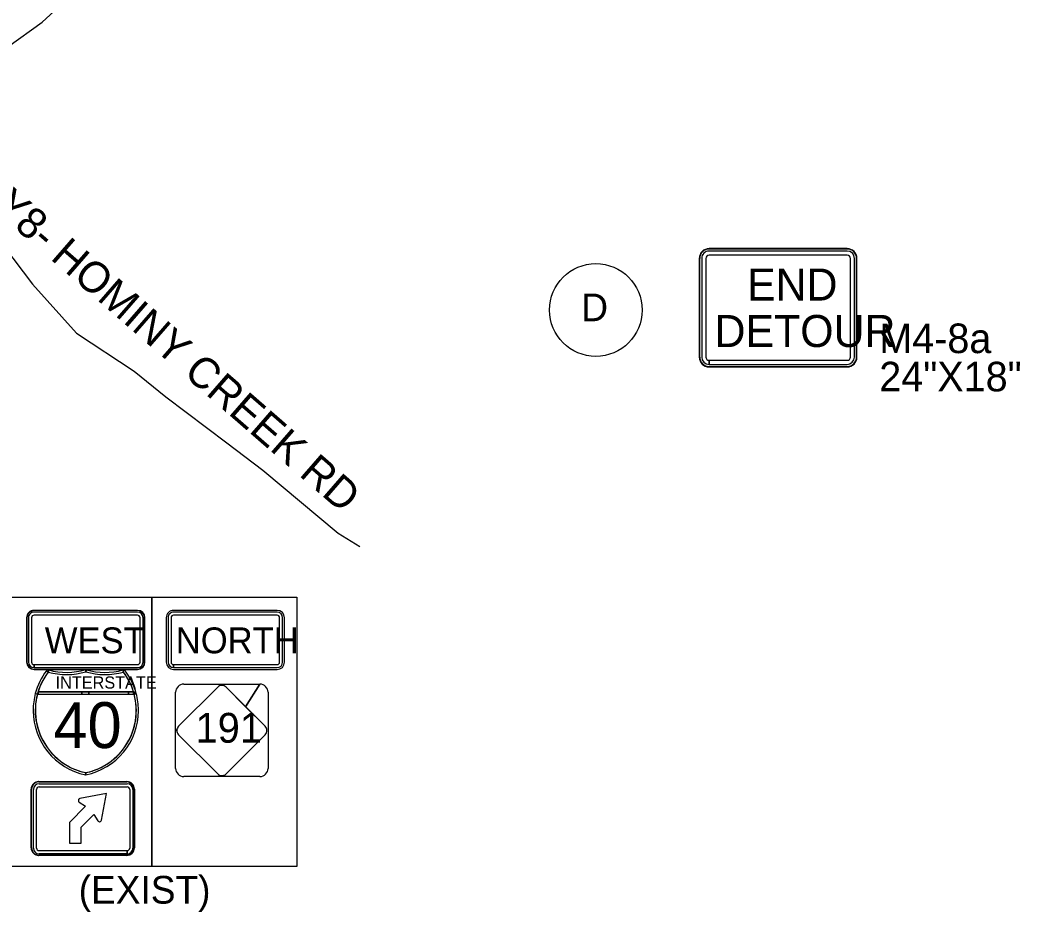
# Model space of a CAD drawing. Extents: x 886234 to 968767, y 455416 to 684046.
# Drawn here: x 917582 to 921641, y 510908 to 514526 of the extents above; entities that cross this region are included whole.
import ezdxf

# ---------------------------------------------------------------- set-up
doc = ezdxf.new("R2010")
doc.units = 0
for name, color, linetype in [('TC DEV SIGN BLACK 239', 7, 'Continuous'), ('TC DEV SIGN BLACK ZERO', 7, 'Continuous'), ('TC DEV SIGN ORANGE', 7, 'Continuous'), ('TC DEV SIGN WHITE', 7, 'Continuous'), ('TC LABEL TEXT', 7, 'Continuous')]:
    doc.layers.add(name, color=color, linetype=linetype)

msp = doc.modelspace()

# ---------------------------------------------------------------- linework, layer by layer
at = {"layer": 'TC DEV SIGN BLACK 239'}
for p, q in [((918059.5, 512124.1), (917639.5, 512124.1)), ((918625.9, 512124.1), (918205.8, 512124.1)), ((918625.9, 512124.1), (918205.8, 512124.1)), ((917617, 512101.6), (917617, 511921.6)), ((917629.5, 512101.6), (917629.5, 511921.6)), ((918059.5, 512111.6), (917639.5, 512111.6)), ((918069.5, 511921.6), (918069.5, 512101.6)), ((918082, 511921.6), (918082, 512101.6)), ((918183.3, 512101.6), (918183.3, 511921.6)), ((918183.3, 512101.6), (918183.3, 511921.6)), ((918195.8, 512101.6), (918195.8, 511921.6)), ((918195.8, 512101.6), (918195.8, 511921.6)), ((918625.9, 512111.6), (918205.8, 512111.6)), ((918625.9, 512111.6), (918205.8, 512111.6)), ((918635.9, 511921.6), (918635.9, 512101.6)), ((918635.9, 511921.6), (918635.9, 512101.6)), ((918648.4, 511921.6), (918648.4, 512101.6)), ((918648.4, 511921.6), (918648.4, 512101.6)), ((917639.5, 511899.1), (917639.5, 511911.6)), ((917639.6, 511911.6), (918059.5, 511911.6)), ((917639.6, 511911.6), (917639.6, 511899.1)), ((917639.6, 511899.1), (918059.5, 511899.1)), ((918205.8, 511899.1), (918205.8, 511911.6)), ((918205.8, 511899.1), (918205.8, 511911.6)), ((918205.9, 511911.6), (918625.9, 511911.6)), ((918205.9, 511911.6), (918205.9, 511899.1)), ((918205.9, 511911.6), (918625.9, 511911.6)), ((918205.9, 511911.6), (918205.9, 511899.1)), ((918205.9, 511899.1), (918625.9, 511899.1)), ((918205.9, 511899.1), (918625.9, 511899.1)), ((918214.1, 511645.6), (918214.1, 511799.1)), ((918214.1, 511645.6), (918214.1, 511799.1)), ((918384.8, 511819.9), (918226, 511661.1)), ((918247.2, 511832.2), (918401.6, 511832.2)), ((918247.2, 511832.2), (918247.2, 511832.2)), ((918247.2, 511832.2), (918556, 511832.2)), ((918247.2, 511832.2), (918247.2, 511832.2)), ((918401.6, 511832.2), (918556, 511832.2)), ((918498.2, 511740.5), (918556, 511832.2)), ((918589.1, 511799.1), (918589.1, 511490.3)), ((918589.1, 511799.1), (918589.1, 511490.3)), ((918577.6, 511661.1), (918498.2, 511740.5)), ((918219, 511645.6), (918214.1, 511645.6)), ((918214.1, 511645.5), (918219, 511645.5)), ((918214.1, 511490.3), (918214.1, 511645.5)), ((918214.1, 511490.3), (918214.1, 511645.5)), ((918226, 511627.1), (918384.8, 511468.3)), ((918418.8, 511468.3), (918577.6, 511627.1)), ((918556, 511457.2), (918247.2, 511457.2)), ((918401.6, 511457.2), (918247.2, 511457.2)), ((918556, 511457.2), (918401.6, 511457.2)), ((917636.9, 511166.8), (917636.9, 511405.3)), ((917649.6, 511166.8), (917649.6, 511405.3)), ((917659.7, 511428.1), (918017.5, 511428.1)), ((917659.7, 511415.5), (918017.5, 511415.5)), ((918027.7, 511405.3), (918027.7, 511166.8)), ((918040.3, 511405.3), (918040.3, 511166.8)), ((918017.4, 511156.6), (917659.7, 511156.6)), ((918017.4, 511156.6), (918017.4, 511144)), ((918017.5, 511144), (918017.5, 511156.6)), ((918017.4, 511144), (917659.7, 511144))]:
    msp.add_line(p, q, dxfattribs=at)
for points in [[(918556, 511832.2), (918498.2, 511740.5), (918418.8, 511819.9)], [(917830.3, 511251.4), (917882.3, 511303.5), (917898.7, 511277.5), (917900.2, 511275.8), (917902, 511274.6), (917904.9, 511273.8), (917906.9, 511274), (917908.7, 511274.5), (917911.1, 511276.2), (917912.5, 511278.2), (917913.2, 511280.3), (917933, 511388), (917825.8, 511367.7), (917824, 511367.2), (917822.8, 511366.4), (917821.3, 511365.1), (917820.2, 511363.6), (917819.5, 511361.4), (917819.5, 511358.7), (917820.2, 511356.4), (917821.5, 511354.4), (917823, 511353.2), (917848.8, 511336.9), (917782.9, 511271)], [(917782.9, 511271), (917782.9, 511187.7), (917830.3, 511187.7), (917830.3, 511251.4)]]:
    msp.add_lwpolyline(points, dxfattribs=at)
for centre, radius, start, end in [((918247.2, 511799.1), 33.1, 90, 180), ((918247.2, 511799.1), 33.1, 90, 180), ((918401.8, 511802.9), 24.1, 93.2102, 135), ((918401.8, 511802.9), 24.1, 45, 93.0763), ((918556, 511799.1), 33.1, 360, 90), ((918556, 511799.1), 33.1, 360, 90), ((918243, 511644.1), 24.1, 176.5595, 225), ((918243, 511644.1), 24.1, 135, 176.407), ((918560.6, 511644.1), 24.1, 1.9293, 45), ((918560.6, 511644.1), 24.1, 315, 1.7382), ((918247.2, 511490.3), 33.1, 180, 270), ((918247.2, 511490.3), 33.1, 180, 270), ((918556, 511490.3), 33.1, 270, 360), ((918556, 511490.3), 33.1, 270, 360), ((918401.8, 511485.3), 24.1, 225, 265.0473), ((918401.8, 511485.3), 24.1, 265.1815, 315)]:
    msp.add_arc(centre, radius, start, end, dxfattribs=at)
for centre, major_axis, start_param, end_param in [((917639.5, 512101.6), (22.5, 0), 1.570796, 3.141593), ((918059.5, 512101.6), (22.5, 0), 0, 1.570796), ((918205.8, 512101.6), (22.5, 0), 1.570796, 3.141593), ((918205.8, 512101.6), (22.5, 0), 1.570796, 3.141593), ((918625.9, 512101.6), (22.5, 0), 0, 1.570796), ((918625.9, 512101.6), (22.5, 0), 0, 1.570796), ((917639.5, 512101.6), (10, 0), 1.570796, 3.141593), ((918059.5, 512101.6), (10, 0), 0, 1.570796), ((918205.8, 512101.6), (10, 0), 1.570796, 3.141593), ((918205.8, 512101.6), (10, 0), 1.570796, 3.141593), ((918625.9, 512101.6), (10, 0), 0, 1.570796), ((918625.9, 512101.6), (10, 0), 0, 1.570796), ((917639.5, 511921.6), (22.5, 0), 3.141593, 4.712389), ((917639.5, 511921.6), (10, 0), 3.141593, 4.712389), ((918059.5, 511921.6), (22.5, 0), 4.712389, 6.283185), ((918059.5, 511921.6), (10, 0), 4.712389, 6.283185), ((918205.8, 511921.6), (22.5, 0), 3.141593, 4.712389), ((918205.8, 511921.6), (22.5, 0), 3.141593, 4.712389), ((918205.8, 511921.6), (10, 0), 3.141593, 4.712389), ((918205.8, 511921.6), (10, 0), 3.141593, 4.712389), ((918625.9, 511921.6), (22.5, 0), 4.712389, 6.283185), ((918625.9, 511921.6), (10, 0), 4.712389, 6.283185), ((918625.9, 511921.6), (22.5, 0), 4.712389, 6.283185), ((918625.9, 511921.6), (10, 0), 4.712389, 6.283185), ((917659.7, 511405.3), (-22.8, 0), 4.712389, 6.283185), ((917659.7, 511405.3), (-10.1, 0), 4.712389, 6.283185), ((918017.5, 511405.3), (-22.8, 0), 3.141593, 4.712389), ((918017.5, 511405.3), (-10.1, 0), 3.141593, 4.712389), ((917659.7, 511166.8), (-22.8, 0), 0, 1.570796), ((917659.7, 511166.8), (-10.1, 0), 0, 1.570796), ((918017.5, 511166.8), (-22.8, 0), 1.570796, 3.141593), ((918017.5, 511166.8), (-10.1, 0), 1.570796, 3.141593)]:
    msp.add_ellipse(centre, major_axis=major_axis, ratio=0.999865, start_param=start_param, end_param=end_param, dxfattribs=at)
at = {"layer": 'TC DEV SIGN BLACK ZERO'}
for p, q in [((920939.2, 513599.1), (920379.1, 513599.1)), ((920379.1, 513597.4), (920379.1, 513597.4)), ((920939.2, 513597.4), (920379.1, 513597.4)), ((920939.2, 513589.1), (920379.1, 513589.1)), ((920939.2, 513597.4), (920939.2, 513597.4)), ((920339.1, 513559.1), (920339, 513159.1)), ((920340.7, 513559.1), (920340.7, 513159.1)), ((920340.7, 513559.1), (920340.7, 513559.1)), ((920349.1, 513559.1), (920349, 513159.1)), ((920365.7, 513559.1), (920365.7, 513159.1)), ((920939.2, 513572.4), (920379.1, 513572.4)), ((920952.5, 513159.1), (920952.5, 513559.1)), ((920969.1, 513159.1), (920969.2, 513559.1)), ((920977.5, 513559.1), (920977.5, 513559.1)), ((920977.5, 513159.1), (920977.5, 513559.1)), ((920979.1, 513159.1), (920979.2, 513559.1)), ((920340.7, 513159.1), (920340.7, 513159.1)), ((920379.1, 513129.1), (920379.1, 513145.8)), ((920379.2, 513145.8), (920939.1, 513145.8)), ((920379.2, 513145.8), (920379.2, 513129.1)), ((920977.5, 513159.1), (920977.5, 513159.1)), ((920379.1, 513119.1), (920379.1, 513120.8)), ((920379.1, 513120.8), (920379.1, 513120.8)), ((920379.1, 513120.8), (920939.1, 513120.8)), ((920379.1, 513120.8), (920379.1, 513119.1)), ((920379.1, 513119.1), (920939.1, 513119.1)), ((920379.2, 513129.1), (920939.1, 513129.1)), ((920939.1, 513120.8), (920939.1, 513120.8)), ((918059.5, 512131.6), (917639.5, 512131.6)), ((917639.5, 512130.3), (917639.5, 512130.4)), ((918059.5, 512130.3), (917639.5, 512130.4)), ((918059.5, 512130.3), (918059.5, 512130.3)), ((917609.5, 512101.6), (917609.5, 511921.6)), ((917610.7, 512101.6), (917610.7, 511921.6)), ((917610.7, 512101.6), (917610.7, 512101.6)), ((918088.3, 512101.6), (918088.3, 512101.6)), ((918088.3, 511921.6), (918088.3, 512101.6)), ((918089.5, 511921.6), (918089.5, 512101.6)), ((917610.7, 511921.6), (917610.7, 511921.6)), ((918088.3, 511921.6), (918088.3, 511921.6)), ((917639.5, 511891.6), (917639.5, 511892.8)), ((917639.5, 511892.8), (917639.5, 511892.8)), ((917639.5, 511892.8), (918059.5, 511892.8)), ((917639.5, 511892.8), (917639.5, 511891.6)), ((917639.5, 511891.6), (918059.5, 511891.6)), ((917696.7, 511881.3), (917699.1, 511889.9)), ((917849.8, 511882.3), (917849.5, 511891.6)), ((917849.7, 511883), (917849.5, 511891.6)), ((917999.9, 511889.9), (918002.4, 511881.3)), ((918059.5, 511892.8), (918059.5, 511892.8)), ((917655.7, 511800.4), (918043.4, 511800.4)), ((917833.2, 511800.4), (917655.7, 511800.4)), ((917861.3, 511800.4), (917833.2, 511800.4)), ((918022.4, 511800.4), (917861.3, 511800.4)), ((918043.4, 511800.4), (918022.4, 511800.4)), ((918054.5, 511793.8), (918043.4, 511800.4)), ((917653.2, 511791.5), (918045.9, 511791.5)), ((917653.2, 511791.5), (917655.7, 511791.5)), ((917655.7, 511791.5), (917833.2, 511791.5)), ((917833.2, 511791.5), (917861.3, 511791.5)), ((917861.3, 511791.5), (918022.4, 511791.5)), ((918022.4, 511791.5), (918043.4, 511791.5)), ((918045.7, 511792.1), (918043.4, 511791.5)), ((918043.4, 511791.5), (918045.9, 511791.5)), ((917635.8, 511727.2), (917635.8, 511724.6)), ((918063.3, 511724.5), (918063.3, 511727.3)), ((917849.5, 511464.1), (917849.5, 511473.2)), ((917658.4, 511436.8), (918016.1, 511436.8)), ((917658.4, 511435.5), (918016.1, 511435.5)), ((917658.4, 511435.5), (917658.4, 511435.5)), ((918016.1, 511435.5), (918016.1, 511435.5)), ((917627.9, 511167.8), (917627.9, 511406.4)), ((917629.2, 511406.4), (917629.2, 511406.4)), ((917629.2, 511167.8), (917629.2, 511406.4)), ((918045.3, 511406.4), (918045.3, 511167.8)), ((918045.3, 511406.4), (918045.3, 511406.4)), ((918046.6, 511406.4), (918046.6, 511167.8)), ((917629.2, 511167.8), (917629.2, 511167.8)), ((918045.3, 511167.8), (918045.3, 511167.8)), ((917658.4, 511138.7), (917658.4, 511138.7)), ((918016.1, 511138.7), (917658.4, 511138.7)), ((918016.1, 511137.4), (917658.4, 511137.4)), ((918016.1, 511137.4), (918016.1, 511138.7)), ((918016.1, 511138.7), (918016.1, 511138.7)), ((918016.1, 511138.7), (918016.1, 511137.4))]:
    msp.add_line(p, q, dxfattribs=at)
for points in [[(917689.6, 511886.7), (917696.7, 511881.3)], [(917696.7, 511881.3), (917689.6, 511886.7)], [(917693.4, 511891.6), (917693.4, 511891.6), (917693.4, 511891.6)], [(917699.1, 511889.9), (917696.7, 511881.3)], [(917849.5, 511882.3), (917849.7, 511883)], [(917849.7, 511891.5), (917849.7, 511883), (917852.3, 511890.8)], [(917852.3, 511890.8), (917849.8, 511882.3)], [(918002.4, 511881.3), (917999.9, 511889.9)], [(918005.7, 511891.6), (918005.7, 511891.6), (918005.7, 511891.6)], [(917655.7, 511800.4), (917655.7, 511791.5)], [(917655.7, 511791.5), (917655.7, 511800.4)], [(917833.2, 511791.5), (917833.2, 511800.4)], [(917833.2, 511800.4), (917833.2, 511791.5)], [(917861.3, 511800.4), (917861.3, 511791.5)], [(917861.3, 511791.5), (917861.3, 511800.4)], [(918022.4, 511791.5), (918022.4, 511800.4)], [(918022.4, 511800.4), (918022.4, 511791.5)], [(918043.4, 511800.4), (918054.5, 511793.8)], [(918043.4, 511791.5), (918043.4, 511800.4)], [(918043.4, 511800.4), (918043.4, 511791.5), (918045.7, 511792.1), (918043.4, 511800.4)], [(917644.5, 511793.8), (917653.2, 511791.5)], [(917653.2, 511791.5), (917644.5, 511793.8)], [(918045.9, 511791.5), (918045.7, 511792.1)], [(918054.5, 511793.8), (918045.9, 511791.5)], [(918045.9, 511791.5), (918054.5, 511793.8)], [(917847.7, 511464.5), (917849.5, 511473.2)], [(917849.5, 511473.2), (917847.7, 511464.5), (917849.5, 511464.1)], [(917849.5, 511473.2), (917849.5, 511464.1)]]:
    msp.add_lwpolyline(points, dxfattribs=at)
for centre, radius, start, end in [((917903, 511725.9), 267.2, 142.9968, 165.2769), ((917903, 511725.9), 258.3, 142.9968, 258.0595), ((917903, 511725.9), 258.3, 142.9968, 165.2769), ((917903, 511725.9), 267.2, 141.6709, 142.9968), ((917771.5, 512147.1), 267.2, 253.0099, 254.2907), ((917771.5, 512147.1), 276.1, 254.2907, 286.4259), ((917771.5, 512147.1), 276.1, 254.2907, 286.4259), ((917771.5, 512147.1), 267.2, 254.2907, 286.9893), ((917927.6, 512147.1), 276.1, 253.5741, 285.7093), ((917796.1, 511725.9), 258.3, 281.9405, 37.0032), ((917927.6, 512147.1), 267.2, 253.0588, 253.6206), ((917927.7, 512146.7), 275.7, 253.5731, 285.7093), ((917927.6, 512147.1), 267.2, 253.6206, 285.7093), ((917927.6, 512147.1), 267.2, 285.7093, 286.9901), ((917796.1, 511725.9), 258.3, 16.7759, 37.0032), ((917796.1, 511725.9), 267.2, 14.7231, 38.3291), ((917903, 511725.9), 258.3, 163.2241, 165.2769), ((917796.1, 511725.9), 258.3, 14.7231, 16.7759), ((917903, 511725.9), 267.2, 165.2769, 179.7177), ((917901.7, 511725.1), 257.3, 165.0438, 258.3001), ((917797.4, 511725.1), 257.3, 281.7196, 14.964), ((917796.1, 511725.9), 267.2, 0.2997, 14.7231), ((917903, 511725.9), 267.2, 180.2823, 258.0591), ((917796.1, 511725.9), 267.2, 281.537, 359.7003), ((917796.1, 511725.9), 258.3, 281.9405, 281.9604), ((917903, 511725.9), 267.2, 258.458, 258.463), ((917796.1, 511725.9), 267.2, 281.5369590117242, 281.53700435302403)]:
    msp.add_arc(centre, radius, start, end, dxfattribs=at)
for centre, major_axis, start_param, end_param in [((920379.1, 513559.1), (40, 0), 1.570796, 3.141593), ((920379.1, 513559.1), (38.3, 0), 1.570796, 3.141593), ((920379.1, 513559.1), (30, 0), 1.570796, 3.141593), ((920939.2, 513559.1), (40, 0), 0, 1.570796), ((920939.2, 513559.1), (38.3, 0), 0, 1.570796), ((920939.2, 513559.1), (30, 0), 0, 1.570796), ((920379.1, 513559.1), (13.3, 0), 1.570796, 3.141593), ((920939.2, 513559.1), (13.3, 0), 0, 1.570796), ((920379.1, 513159.1), (40, 0), 3.141593, 4.712389), ((920379.1, 513159.1), (38.3, 0), 3.141593, 4.712389), ((920379.1, 513159.1), (30, 0), 3.141593, 4.712389), ((920379.1, 513159.1), (13.3, 0), 3.141593, 4.712389), ((920939.1, 513159.1), (30, 0), 4.712389, 6.283185), ((920939.1, 513159.1), (13.3, 0), 4.712389, 6.283185), ((920939.1, 513159.1), (40, 0), 4.712389, 6.283185), ((920939.1, 513159.1), (38.3, 0), 4.712389, 6.283185), ((917639.5, 512101.6), (30, 0), 1.570796, 3.141593), ((917639.5, 512101.6), (28.8, 0), 1.570796, 3.141593), ((918059.5, 512101.6), (30, 0), 0, 1.570796), ((918059.5, 512101.6), (28.8, 0), 0, 1.570796), ((917639.5, 511921.6), (30, 0), 3.141593, 4.712389), ((917639.5, 511921.6), (28.8, 0), 3.141593, 4.712389), ((918059.5, 511921.6), (30, 0), 4.712389, 6.283185), ((918059.5, 511921.6), (28.8, 0), 4.712389, 6.283185), ((917658.4, 511406.4), (-30.4, 0), 4.712389, 6.283185), ((917658.4, 511406.4), (-29.2, 0), 4.712389, 6.283185), ((918016.1, 511406.4), (-30.4, 0), 3.141593, 4.712389), ((918016.1, 511406.4), (-29.2, 0), 3.141593, 4.712389), ((917658.4, 511167.8), (-30.4, 0), 0, 1.570796), ((917658.4, 511167.8), (-29.2, 0), 0, 1.570796), ((918016.1, 511167.8), (-30.4, 0), 1.570796, 3.141593), ((918016.1, 511167.8), (-29.2, 0), 1.570796, 3.141593)]:
    msp.add_ellipse(centre, major_axis=major_axis, ratio=0.999865, start_param=start_param, end_param=end_param, dxfattribs=at)
at = {"layer": 'TC DEV SIGN ORANGE'}
for p, q in [((920939.2, 513599.1), (920379.1, 513599.1)), ((920339.1, 513559.1), (920339, 513159.1)), ((920979.1, 513159.1), (920979.2, 513559.1)), ((920379.1, 513119.1), (920939.1, 513119.1))]:
    msp.add_line(p, q, dxfattribs=at)
for centre, start_param, end_param in [((920379.1, 513559.1), 1.570796, 3.141593), ((920939.2, 513559.1), 0, 1.570796), ((920379.1, 513159.1), 3.141593, 4.712389), ((920939.1, 513159.1), 4.712389, 6.283185)]:
    msp.add_ellipse(centre, major_axis=(40, 0), ratio=0.999865, start_param=start_param, end_param=end_param, dxfattribs=at)
at = {"layer": 'TC DEV SIGN WHITE'}
for p, q in [((918059.5, 512131.6), (917639.5, 512131.6)), ((918625.9, 512131.6), (918205.8, 512131.6)), ((917609.5, 512101.6), (917609.5, 511921.6)), ((918089.5, 511921.6), (918089.5, 512101.6)), ((918175.8, 512101.6), (918175.8, 511921.6)), ((918655.9, 511921.6), (918655.9, 512101.6)), ((917639.5, 511891.6), (918059.5, 511891.6)), ((918205.8, 511891.6), (918625.9, 511891.6)), ((918226, 511661.1), (918384.8, 511819.9)), ((918384.8, 511819.9), (918226, 511661.1)), ((918418.8, 511819.9), (918577.6, 511661.1)), ((918418.8, 511819.9), (918418.8, 511819.9)), ((918577.6, 511661.1), (918418.8, 511819.9)), ((918219, 511645.5), (918219, 511645.5)), ((918384.8, 511468.3), (918226, 511627.1)), ((918226, 511627.1), (918384.8, 511468.3)), ((918577.6, 511627.1), (918418.8, 511468.3)), ((918418.8, 511468.3), (918577.6, 511627.1)), ((917658.2, 511436.9), (918016, 511436.9)), ((917627.8, 511167.9), (917627.8, 511406.5)), ((918046.4, 511406.5), (918046.4, 511167.9)), ((918016, 511137.5), (917658.2, 511137.5))]:
    msp.add_line(p, q, dxfattribs=at)
for points in [[(918400.5, 511826.9), (918400.4, 511826.9)], [(918219, 511645.6), (918219, 511645.6), (918219, 511645.5)], [(918584.7, 511644.8), (918584.6, 511644.9)], [(918399.7, 511461.3), (918399.8, 511461.3)]]:
    msp.add_lwpolyline(points, dxfattribs=at)
for centre, start, end in [((918401.8, 511802.9), 93.2102, 135), ((918401.8, 511802.9), 93.2102, 135), ((918401.8, 511802.9), 45, 93.0763), ((918401.8, 511802.9), 45, 93.0763), ((918243, 511644.1), 176.5595, 225), ((918243, 511644.1), 176.5602, 225), ((918243, 511644.1), 135, 176.407), ((918243, 511644.1), 135, 176.407), ((918560.6, 511644.1), 1.9293, 45), ((918560.6, 511644.1), 1.9293, 45), ((918560.6, 511644.1), 315, 1.7382), ((918560.6, 511644.1), 315, 1.7382), ((918401.8, 511485.3), 225, 265.0473), ((918401.8, 511485.3), 225, 265.0473), ((918401.8, 511485.3), 265.1815, 315), ((918401.8, 511485.3), 265.1815, 315)]:
    msp.add_arc(centre, 24.1, start, end, dxfattribs=at)
for centre, major_axis, start_param, end_param in [((917639.5, 512101.6), (30, 0), 1.570796, 3.141593), ((918059.5, 512101.6), (30, 0), 0, 1.570796), ((918205.8, 512101.6), (30, 0), 1.570796, 3.141593), ((918625.9, 512101.6), (30, 0), 0, 1.570796), ((917639.5, 511921.6), (30, 0), 3.141593, 4.712389), ((918059.5, 511921.6), (30, 0), 4.712389, 6.283185), ((918205.8, 511921.6), (30, 0), 3.141593, 4.712389), ((918625.9, 511921.6), (30, 0), 4.712389, 6.283185), ((917658.2, 511406.5), (-30.4, 0), 4.712389, 6.283185), ((918016, 511406.5), (-30.4, 0), 3.141593, 4.712389), ((917658.2, 511167.9), (-30.4, 0), 0, 1.570796), ((918016, 511167.9), (-30.4, 0), 1.570796, 3.141593)]:
    msp.add_ellipse(centre, major_axis=major_axis, ratio=0.999865, start_param=start_param, end_param=end_param, dxfattribs=at)
at = {"layer": 'TC LABEL TEXT'}
for points in [[(917006.6, 514128.8), (917209.3, 514224.9), (917533.5, 514417.1), (917672.4, 514517.1), (917836.1, 514669.7), (917946.7, 514775.6), (918339, 515147.1)], [(917057.6, 514176.4), (917138.1, 514097.6), (917190.4, 514043.6), (917358.5, 513815.8), (917633.5, 513455.2), (917812, 513256.3), (918045.7, 513101.4), (918174.4, 512997.9), (918422.4, 512811.2), (918567.4, 512700.5), (918873.9, 512444.5), (918961.7, 512391)]]:
    msp.add_lwpolyline(points, dxfattribs=at)
for points in [[(917530.2, 512185), (918117.9, 512185), (918117.9, 511091.8), (917530.2, 511091.8)], [(918117.9, 512185), (918705.6, 512185), (918705.6, 511091.8), (918117.9, 511091.8)]]:
    msp.add_lwpolyline(points, close=True, dxfattribs=at)
msp.add_circle((919919.5, 513349.9), 188.1, dxfattribs=at)

# ---------------------------------------------------------------- texts
at = {"layer": 'TC DEV SIGN BLACK 239'}
for s, height, p in [('WEST', 105, (917683.1, 511957.3)), ('NORTH', 105, (918214.6, 511957.3)), ('191', 120.97, (918294.7, 511594.6))]:
    msp.add_text(s, height=height, rotation=360, dxfattribs=at).set_placement(p)
at = {"layer": 'TC DEV SIGN BLACK ZERO'}
for s, height, p in [('END', 130, (920533.1, 513388.3)), ('DETOUR', 130, (920401.3, 513199.8)), ('M4-8a', 120, (921069.7, 513175.1)), ('24"X18"', 120, (921069.7, 513019.9)), ('INTERSTATE', 49.28, (917727.1, 511814.2)), ('40', 186.16, (917718.2, 511572.9))]:
    msp.add_text(s, height=height, rotation=360, dxfattribs=at).set_placement(p)
at = {"layer": 'TC LABEL TEXT'}
msp.add_text('-Y8- HOMINY CREEK RD', height=125, rotation=318.9754, dxfattribs=at).set_placement((917428.9, 513795.9))
for s, p in [('D', (919860.4, 513304.4)), ('(EXIST)', (917820.6, 510941.8))]:
    msp.add_text(s, height=112.5, dxfattribs=at).set_placement(p)

doc.saveas('drawing.dxf')
